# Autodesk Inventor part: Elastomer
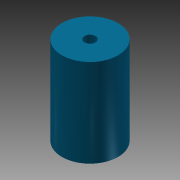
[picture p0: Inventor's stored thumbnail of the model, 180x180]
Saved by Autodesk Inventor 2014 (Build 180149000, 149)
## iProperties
Shininess: 64.0
Length Units: 11272
Angle Units: 11279
Time Units: 11290
Mass Units: 11286
Length Display Precision: 3
Angle Display Precision: 2
Compacted: True
Created: 2001-11
Part Number: Elastomer
Document SubType Name: Modeling
Designer: Autodesk, Inc.
Mass: 3.41477 g
Surface Area: 15.0056 cm^2
Volume: 3.41477 cm^3
Density: 1 g/cm^3
Material: Generic
Appearance: Sky Blue Dark
Density: 0.0
Volumn: 0.0
Area: 0.0
PropertySet Name: Model Information
Control State: 0
Master: False
Checked Out: False
Author: Autodesk, Inc.
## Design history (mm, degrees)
sketch "Sketch1"
  geometry: L1 (144.661, 147.973)-(150.376, 147.973); L2 (150.376, 147.973)-(150.376, 125.621); L3 (150.376, 125.621)-(144.661, 125.621); L4 (144.661, 147.973)-(144.661, 125.621); L5 (143.264, 91.328)-(143.264, 147.973); L6 (143.264, 91.328)-(143.264, 147.973)
  constraints: 12 end point, 3 vertical, 2 horizontal, 1 other
  dimensions: "d1" = 22.352 distance of L1.end L2.end; "d3" = 7.112 distance of L5.end L1.end
revolve "RevolutionFull1" sketch "Sketch1" stored, may be unused: angle "d4" = 360 deg
body "Solid1"
other parameters: "d0" = 22.352 (derived), "d2" = 7.112 (derived)
